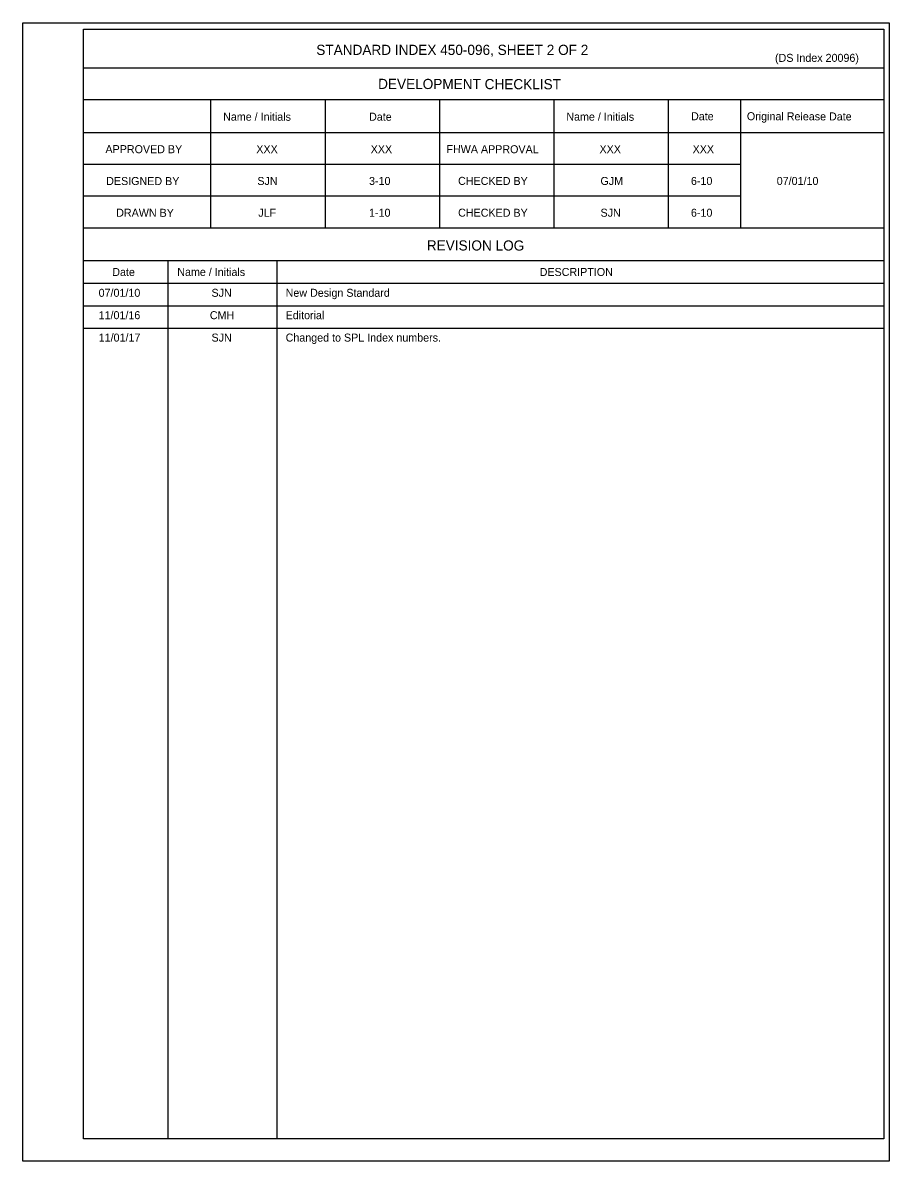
# Model space of a CAD drawing. Extents: x 4.6 to 40.7, y -0.4 to 17.4.
# Drawn here: x 29.79 to 40.7, y 2.25 to 16.59 of the extents above; entities that cross this region are included whole.
import ezdxf

# ---------------------------------------------------------------- set-up
doc = ezdxf.new("R2010")
doc.units = 0
for name, color, linetype in [('Border', 7, 'Continuous'), ('Dimension', 7, 'Continuous'), ('PlotBorder_dp', 7, 'Continuous'), ('TextStructures', 7, 'Continuous')]:
    doc.layers.add(name, color=color, linetype=linetype)

msp = doc.modelspace()

# ---------------------------------------------------------------- linework, layer by layer
at = {"layer": 'Border'}
for p, q in [((40.633, 16.015), (30.559, 16.015)), ((40.633, 15.615), (30.559, 15.615)), ((32.159, 15.615), (32.159, 14.002)), ((33.599, 15.615), (33.599, 14.002)), ((35.039, 15.615), (35.039, 14.002)), ((36.479, 15.615), (36.479, 14.002)), ((37.919, 15.615), (37.919, 14.002)), ((38.827, 15.615), (38.827, 14.002)), ((40.633, 15.202), (30.559, 15.202)), ((38.827, 14.802), (30.559, 14.802)), ((38.827, 14.402), (30.559, 14.402)), ((40.633, 14.002), (30.559, 14.002)), ((40.633, 13.588), (30.559, 13.588)), ((31.62, 13.588), (31.62, 2.534)), ((32.991, 13.588), (32.991, 2.534)), ((40.633, 13.306), (30.559, 13.306))]:
    msp.add_line(p, q, dxfattribs=at)
msp.add_lwpolyline([(30.56, 16.506), (40.633, 16.506), (40.633, 2.534), (30.56, 2.534)], close=True, dxfattribs=at)
at = {"layer": 'Dimension'}
for p, q in [((30.56, 13.024), (40.633, 13.024)), ((30.56, 12.742), (40.633, 12.742))]:
    msp.add_line(p, q, dxfattribs=at)
at = {"layer": 'PlotBorder_dp'}
msp.add_line((29.794, 2.254), (29.794, 2.254), dxfattribs=at)
msp.add_lwpolyline([(29.794, 16.587), (40.701, 16.587), (40.701, 2.254), (29.794, 2.254)], close=True, dxfattribs=at)

# ---------------------------------------------------------------- texts
at = {"layer": 'TextStructures'}
for s, height, p in [('STANDARD INDEX 450-096, SHEET 2 OF 2', 0.128, (33.489, 16.182)), ('(DS Index 20096)', 0.1008, (39.263, 16.095)), ('XXX', 0.1008, (32.734, 14.945)), ('XXX', 0.1008, (34.174, 14.945)), ('XXX', 0.1008, (37.054, 14.945)), ('XXX', 0.1008, (38.226, 14.945)), ('SJN', 0.1008, (32.747, 14.545)), ('3-10', 0.1008, (34.153, 14.545)), ('GJM', 0.1008, (37.066, 14.545)), ('6-10', 0.1008, (38.205, 14.545)), ('07/01/10', 0.1008, (39.285, 14.545)), ('JLF', 0.1008, (32.759, 14.145)), ('1-10', 0.1008, (34.153, 14.145)), ('SJN', 0.1008, (37.067, 14.145)), ('6-10', 0.1008, (38.205, 14.145)), ('DESCRIPTION', 0.1008, (36.301, 13.399)), ('07/01/10', 0.1008, (30.749, 13.137)), ('SJN', 0.1008, (32.17, 13.137)), ('New Design Standard', 0.1008, (33.103, 13.137)), ('11/01/16', 0.1008, (30.749, 12.855)), ('CMH', 0.1008, (32.149, 12.855)), ('Editorial', 0.1008, (33.103, 12.855)), ('11/01/17', 0.1008, (30.75, 12.573)), ('SJN', 0.1008, (32.17, 12.573)), ('Changed to SPL Index numbers.', 0.1008, (33.103, 12.573))]:
    msp.add_text(s, height=height, dxfattribs=at).set_placement(p)
for s, height, p in [('DEVELOPMENT CHECKLIST', 0.128, (34.267, 15.754)), ('Name / Initials', 0.1008, (32.316, 15.355)), ('Date', 0.1008, (34.153, 15.354)), ('Name / Initials', 0.1008, (36.636, 15.355)), ('Date', 0.1008, (38.206, 15.36)), ('Original Release Date', 0.1008, (38.909, 15.36)), ('APPROVED BY', 0.1008, (30.835, 14.946)), ('FHWA APPROVAL', 0.1008, (35.127, 14.946)), ('DESIGNED BY', 0.1008, (30.844, 14.545)), ('CHECKED BY', 0.1008, (35.274, 14.546)), ('DRAWN BY', 0.1008, (30.97, 14.145)), ('CHECKED BY', 0.1008, (35.274, 14.146)), ('REVISION LOG', 0.128, (34.88, 13.721)), ('Date', 0.1008, (30.921, 13.399)), ('Name / Initials', 0.1008, (31.739, 13.4))]:
    msp.add_text(s, height=height, rotation=359.8756, dxfattribs=at).set_placement(p)

doc.saveas('drawing.dxf')
